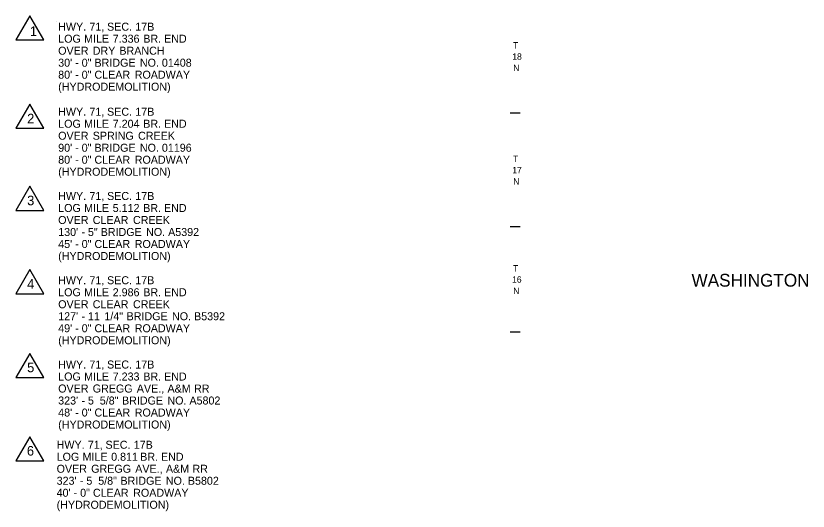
# Model space of a CAD drawing. Extents: x -17668 to 16999, y -17303 to 5867.
# Drawn here: x -17202 to -9780, y -3437 to 1206 of the extents above; entities that cross this region are included whole.
import ezdxf

# ---------------------------------------------------------------- set-up
doc = ezdxf.new("R2010")
doc.units = 0
for name, color, linetype in [('2', 7, 'Continuous'), ('48', 7, 'Continuous'), ('Default', 7, 'Continuous')]:
    doc.layers.add(name, color=color, linetype=linetype)

msp = doc.modelspace()

# ---------------------------------------------------------------- linework, layer by layer
at = {"layer": '48'}
for p, q in [((-17071, 1206.1), (-17201.6, 979.9)), ((-16940.4, 979.9), (-17071, 1206.1)), ((-16819.5, 1156.8), (-16819.5, 1156.8)), ((-17201.6, 979.9), (-16940.4, 979.9)), ((-17071, 379.1), (-17201.6, 152.9)), ((-16940.4, 152.9), (-17071, 379.1)), ((-17201.6, 152.9), (-16940.4, 152.9)), ((-17071, -390.7), (-17201.6, -616.9)), ((-16940.4, -616.9), (-17071, -390.7)), ((-17201.6, -616.9), (-16940.4, -616.9)), ((-17071, -1172.3), (-17201.6, -1398.6)), ((-16940.4, -1398.6), (-17071, -1172.3)), ((-17201.6, -1398.6), (-16940.4, -1398.6)), ((-17071, -1957.7), (-17201.6, -2183.9)), ((-16940.4, -2183.9), (-17071, -1957.7)), ((-17201.6, -2183.9), (-16940.4, -2183.9)), ((-17071, -2739.3), (-17201.6, -2965.5)), ((-16940.4, -2965.5), (-17071, -2739.3)), ((-16819.5, -2776.5), (-16819.5, -2776.5)), ((-17201.6, -2965.5), (-16940.4, -2965.5))]:
    msp.add_line(p, q, dxfattribs=at)
at = {"layer": 'Default'}
for p, q in [((-12477.3, 292.4), (-12572.3, 292.4)), ((-12477.3, -772.4), (-12572.3, -772.4)), ((-12477.3, -1758.6), (-12572.3, -1758.6))]:
    msp.add_line(p, q, dxfattribs=at)

# ---------------------------------------------------------------- texts
at = {"layer": '2'}
for s, p in [('T', (-12544.4, 899.4)), ('18', (-12551.7, 794.4)), ('N', (-12543.4, 689.4)), ('T', (-12544.4, -165)), ('17', (-12551.7, -270)), ('N', (-12543.4, -375)), ('T', (-12544.4, -1190.5)), ('16', (-12553.4, -1295.5)), ('N', (-12543.4, -1400.5))]:
    msp.add_text(s, height=60, rotation=360, dxfattribs=at).set_placement(p)
msp.add_text('WASHINGTON', height=120, dxfattribs=at).set_placement((-10872.5, -1332.3))
at = {"layer": '48'}
for s, p in [('1', (-17070.2, 1017.5)), ('2', (-17095.7, 198.5)), ('3', (-17095.7, -569.3)), ('4', (-17095.7, -1351.7)), ('5', (-17095.7, -2134.1)), ('6', (-17098.2, -2915.8))]:
    msp.add_text(s, height=90, dxfattribs=at).set_placement(p)
at = {"layer": 'Default'}
for s, p in [('HWY.', (-16804.9, 1066.8)), (' 71,', (-16540.4, 1066.8)), (' SEC.', (-16375, 1066.8)), (' 17B', (-16110.5, 1066.8)), ('LOG', (-16804.9, 954.3)), (' MILE', (-16590.2, 954.3)), (' 7.336', (-16322.1, 954.3)), (' BR.', (-16035.7, 954.3)), (' END', (-15841, 954.3)), ('OVER', (-16804.9, 841.8)), (' DRY', (-16509.3, 841.8)), (' BRANCH', (-16259.7, 841.8)), ("30'", (-16804.9, 729.3)), (' -', (-16673.3, 729.3)), (' 0"', (-16612.6, 729.3)), (' BRIDGE', (-16492.9, 729.3)), (' NO.', (-16067.6, 729.3)), (' 01408', (-15861.4, 729.3)), ("80'", (-16804.9, 616.8)), (' 0"', (-16612.6, 616.8)), (' CLEAR', (-16492.9, 616.8)), (' ROADWAY', (-16115.8, 616.8)), (' -', (-16673.3, 616.8)), ('(HYDRODEMOLITION)', (-16804.9, 504.3)), ('HWY.', (-16804.9, 269.8)), (' 71,', (-16540.4, 269.8)), (' SEC.', (-16375, 269.8)), (' 17B', (-16110.5, 269.8)), ('LOG', (-16804.9, 157.3)), (' MILE', (-16590.2, 157.3)), (' 7.204', (-16322.1, 157.3)), (' BR.', (-16036, 157.3)), (' END', (-15841.4, 157.3)), ('OVER', (-16804.9, 44.8)), (' SPRING', (-16509.3, 44.8)), (' CREEK', (-16084.9, 44.8)), ("90'", (-16804.9, -67.7)), (' 0"', (-16612.6, -67.7)), (' BRIDGE', (-16492.9, -67.7)), (' NO.', (-16067.6, -67.7)), (' 01196', (-15861.4, -67.7)), (' -', (-16673.3, -67.7)), ("80'", (-16804.9, -180.2)), (' -', (-16673.3, -180.2)), (' 0"', (-16612.6, -180.2)), (' CLEAR', (-16492.9, -180.2)), (' ROADWAY', (-16115.8, -180.2)), ('(HYDRODEMOLITION)', (-16804.9, -292.7)), ('HWY.', (-16804.9, -520)), (' 71,', (-16540.4, -520)), (' SEC.', (-16375, -520)), (' 17B', (-16110.5, -520)), ('LOG', (-16804.9, -632.5)), (' MILE', (-16590.2, -632.5)), (' 5.112', (-16322.1, -632.5)), (' BR.', (-16036.5, -632.5)), (' END', (-15841.8, -632.5)), ('OVER', (-16804.9, -745)), (' CLEAR', (-16509.3, -745)), (' CREEK', (-16132.2, -745)), ("130'", (-16804.9, -857.5)), (' 5"', (-16554.3, -857.5)), (' BRIDGE', (-16434.7, -857.5)), (' NO.', (-16009.4, -857.5)), (' A5392', (-15803.1, -857.5)), (' -', (-16615, -857.5)), ("45'", (-16804.9, -970)), (' -', (-16673.3, -970)), (' 0"', (-16612.6, -970)), (' CLEAR', (-16492.9, -970)), (' ROADWAY', (-16115.8, -970)), ('(HYDRODEMOLITION)', (-16804.9, -1082.5)), ('HWY.', (-16804.9, -1309.7)), (' 71,', (-16540.4, -1309.7)), (' SEC.', (-16375, -1309.7)), (' 17B', (-16110.5, -1309.7)), ('LOG', (-16804.9, -1422.2)), (' MILE', (-16590.2, -1422.2)), (' 2.986', (-16322.1, -1422.2)), (' BR.', (-16035.7, -1422.2)), (' END', (-15841, -1422.2)), ('OVER', (-16804.9, -1534.7)), (' CLEAR', (-16509.3, -1534.7)), (' CREEK', (-16132.2, -1534.7)), ("127'", (-16804.9, -1647.2)), (' -', (-16615, -1647.2)), (' 11', (-16554.3, -1647.2)), ('  1/4"', (-16428, -1647.2)), (' BRIDGE', (-16191.9, -1647.2)), (' NO.', (-15766.6, -1647.2)), (' B5392', (-15560.3, -1647.2)), ("49'", (-16804.9, -1759.7)), (' 0"', (-16612.6, -1759.7)), (' CLEAR', (-16492.9, -1759.7)), (' ROADWAY', (-16115.8, -1759.7)), (' -', (-16673.3, -1759.7)), ('(HYDRODEMOLITION)', (-16804.9, -1872.2)), ('HWY.', (-16804.9, -2099.5)), (' 71,', (-16540.4, -2099.5)), (' SEC.', (-16375, -2099.5)), (' 17B', (-16110.5, -2099.5)), ('LOG', (-16804.9, -2212)), (' MILE', (-16590.2, -2212)), (' 7.233', (-16322.1, -2212)), (' BR.', (-16035.7, -2212)), (' END', (-15841, -2212)), ('OVER', (-16804.9, -2324.5)), (' GREGG', (-16509.3, -2324.5)), (' AVE.,', (-16096.6, -2324.5)), (' A&M', (-15808.9, -2324.5)), (' RR', (-15560.6, -2324.5)), ("323'", (-16804.9, -2437)), (' 5', (-16554.3, -2437)), ('  5/8"', (-16471.1, -2437)), (' BRIDGE', (-16235.1, -2437)), (' NO.', (-15809.7, -2437)), (' A5802', (-15603.5, -2437)), (' -', (-16615, -2437)), ("48'", (-16804.9, -2549.5)), (' -', (-16673.3, -2549.5)), (' 0"', (-16612.6, -2549.5)), (' CLEAR', (-16492.9, -2549.5)), (' ROADWAY', (-16115.8, -2549.5)), ('(HYDRODEMOLITION)', (-16804.9, -2662)), ('HWY.', (-16819.5, -2851.5)), (' 71,', (-16555, -2851.5)), (' SEC.', (-16389.7, -2851.5)), (' 17B', (-16125.1, -2851.5)), ('LOG', (-16819.5, -2964)), (' MILE', (-16604.8, -2964)), (' 0.811', (-16336.7, -2964)), (' BR.', (-16064.8, -2964)), (' END', (-15870.2, -2964)), ('OVER', (-16819.5, -3076.5)), (' GREGG', (-16523.9, -3076.5)), (' AVE.,', (-16111.2, -3076.5)), (' A&M', (-15823.5, -3076.5)), (' RR', (-15575.2, -3076.5)), ("323'", (-16819.5, -3189)), (' 5', (-16568.9, -3189)), ('  5/8"', (-16485.8, -3189)), (' BRIDGE', (-16249.7, -3189)), (' NO.', (-15824.4, -3189)), (' B5802', (-15618.1, -3189)), (' -', (-16629.6, -3189)), ("40'", (-16819.5, -3301.5)), (' 0"', (-16627.2, -3301.5)), (' CLEAR', (-16507.5, -3301.5)), (' ROADWAY', (-16130.4, -3301.5)), ('(HYDRODEMOLITION)', (-16819.5, -3414)), (' -', (-16687.9, -3301.5))]:
    msp.add_text(s, height=75, dxfattribs=at).set_placement(p)

doc.saveas('drawing.dxf')
